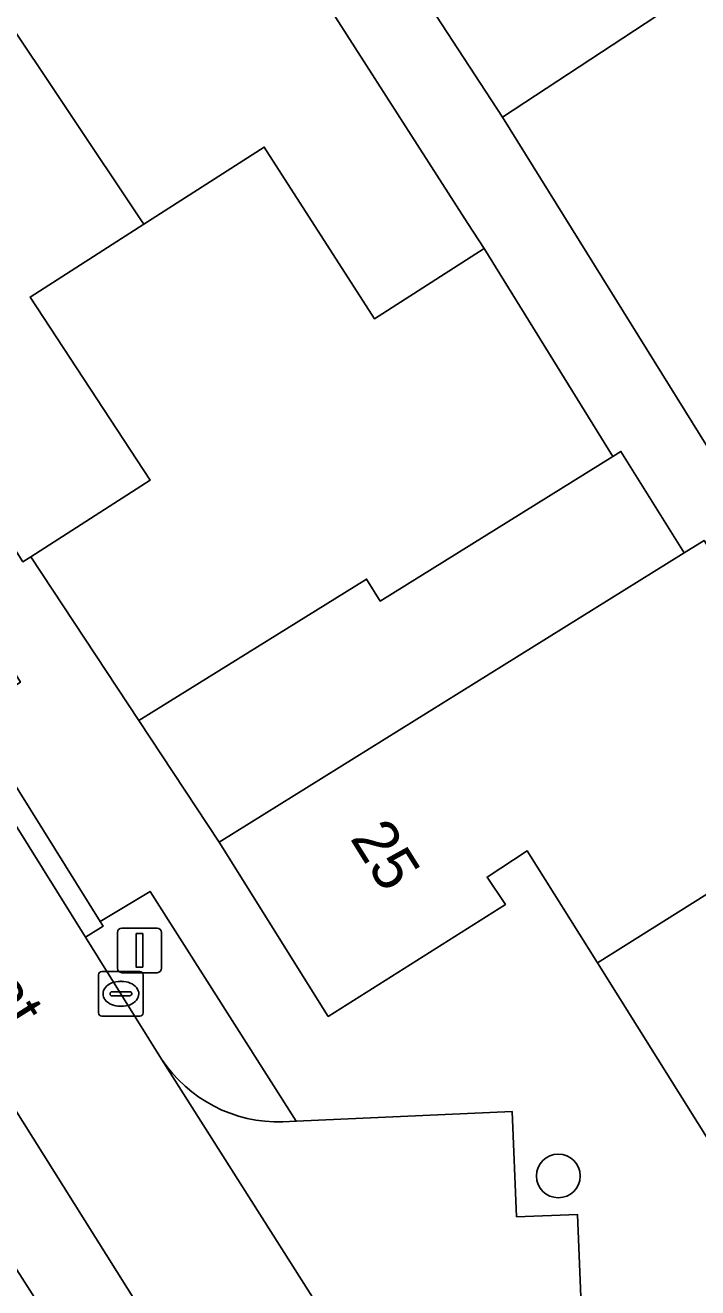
# Model space of a CAD drawing. Extents: x 161798 to 162385, y 382315 to 382833.
# Drawn here: x 162067.75 to 162082.82, y 382537.31 to 382565.6 of the extents above; entities that cross this region are included whole.
import ezdxf

# ---------------------------------------------------------------- set-up
doc = ezdxf.new("R2010")
doc.units = 0
for name, color, linetype in [('IMGEO_Boom', 7, 'Continuous'), ('IMGEO_Erf', 7, 'Continuous'), ('IMGEO_Groenvoorziening', 7, 'Continuous'), ('IMGEO_Kolk', 7, 'Continuous'), ('IMGEO_Lichtmast', 7, 'Continuous'), ('IMGEO_Muur', 7, 'Continuous'), ('IMGEO_Openbare_ruimte_label', 7, 'Continuous'), ('IMGEO_Pand', 7, 'Continuous'), ('IMGEO_Pand_nummerreeks', 7, 'Continuous'), ('IMGEO_Parkeervlak_open', 7, 'Continuous'), ('IMGEO_Rijbaan_lokaal_open', 7, 'Continuous'), ('IMGEO_Voetpad_open', 7, 'Continuous')]:
    doc.layers.add(name, color=color, linetype=linetype)

msp = doc.modelspace()

# ---------------------------------------------------------------- linework, layer by layer
at = {"layer": 'IMGEO_Boom'}
msp.add_circle((162079.693, 382539.814), 0.489, dxfattribs=at)
at = {"layer": 'IMGEO_Erf'}
msp.add_lwpolyline([(162102.649, 382579.449), (162098.622, 382576.803), (162096.601, 382575.476), (162088.533, 382570.177), (162078.441, 382563.548), (162083.732, 382555.037), (162084.772, 382555.684), (162083.299, 382557.955), (162092.219, 382563.711), (162093.688, 382561.433), (162094.761, 382562.125), (162093.279, 382564.418), (162096.865, 382566.737), (162098.358, 382564.461), (162096.539, 382563.28), (162097.699, 382561.493), (162099.947, 382562.953)], dxfattribs=at)
msp.add_lwpolyline([(162078.029, 382560.599), (162075.575, 382559.025), (162073.107, 382562.874), (162070.408, 382561.144), (162067.86, 382559.511), (162070.553, 382555.41), (162067.877, 382553.694), (162070.298, 382550.02), (162075.398, 382553.192), (162075.704, 382552.7), (162080.915, 382555.941)], close=True, dxfattribs=at)
at = {"layer": 'IMGEO_Groenvoorziening'}
for points in [[(162073.52, 382541.026), (162073.822, 382541.04), (162070.549, 382546.192), (162069.427, 382545.515)], [(162069.427, 382545.515), (162069.493, 382545.409), (162069.1, 382545.165), (162070.806, 382542.435)]]:
    msp.add_lwpolyline(points, dxfattribs=at)
msp.add_arc((162073.428, 382544.166), 3.142, 213.4405, 271.6865, dxfattribs=at)
at = {"layer": 'IMGEO_Kolk'}
for p, q in [((162069.393, 382543.47), (162069.393, 382544.322)), ((162069.468, 382544.396), (162070.32, 382544.396)), ((162069.881, 382544.176), (162069.906, 382544.176)), ((162070.394, 382544.322), (162070.394, 382543.47)), ((162069.652, 382543.89), (162069.652, 382543.902)), ((162069.695, 382543.939), (162070.093, 382543.939)), ((162070.136, 382543.902), (162070.136, 382543.89)), ((162070.09, 382543.853), (162069.692, 382543.853)), ((162069.904, 382543.616), (162069.879, 382543.616)), ((162070.32, 382543.396), (162069.468, 382543.396))]:
    msp.add_line(p, q, dxfattribs=at)
for points in [[(162069.393, 382543.47), (162069.393, 382544.322)], [(162069.468, 382544.396), (162070.32, 382544.396)], [(162070.394, 382544.322), (162070.394, 382543.47)], [(162070.32, 382543.396), (162069.468, 382543.396)]]:
    msp.add_lwpolyline(points, dxfattribs=at)
for centre, radius, start, end in [((162069.47, 382544.32), 0.0765, 91.552, 178.448), ((162069.47, 382544.32), 0.0765, 91.552, 178.448), ((162070.318, 382544.32), 0.0765, 1.552, 88.448), ((162070.318, 382544.32), 0.0765, 1.552, 88.448), ((162069.692, 382543.899), 0.0403, 85.8775, 175.7526), ((162069.689, 382543.889), 0.0366, 178.938, 274.7102), ((162070.093, 382543.896), 0.043, 264.8664, 352.4533), ((162070.097, 382543.901), 0.0386, 1.7309, 96.639), ((162069.47, 382543.472), 0.0765, 181.552, 268.448), ((162069.47, 382543.472), 0.0765, 181.552, 268.448), ((162070.318, 382543.472), 0.0765, 271.552, 358.448), ((162070.318, 382543.472), 0.0765, 271.552, 358.448)]:
    msp.add_arc(centre, radius, start, end, dxfattribs=at)
for centre, major_axis, ratio, start_param, end_param in [((162069.88, 382543.896), (-0.387, 0.002), 0.722429, 4.712389, 7.853982), ((162069.905, 382543.896), (-0.39, 0.002), 0.717154, 1.570796, 4.712389)]:
    msp.add_ellipse(centre, major_axis=major_axis, ratio=ratio, start_param=start_param, end_param=end_param, dxfattribs=at)
at = {"layer": 'IMGEO_Lichtmast'}
for p, q in [((162069.914, 382545.37), (162070.704, 382545.37)), ((162070.704, 382545.37), (162069.914, 382545.37)), ((162069.814, 382544.47), (162069.814, 382545.27)), ((162069.814, 382545.27), (162069.814, 382544.47)), ((162070.804, 382545.27), (162070.804, 382544.47)), ((162070.804, 382544.47), (162070.804, 382545.27)), ((162070.704, 382544.37), (162069.914, 382544.37)), ((162069.914, 382544.37), (162070.704, 382544.37))]:
    msp.add_line(p, q, dxfattribs=at)
msp.add_lwpolyline([(162070.234, 382545.245), (162070.384, 382545.245), (162070.384, 382544.495), (162070.234, 382544.495), (162070.234, 382545.245)], dxfattribs=at)
for centre, start, end in [((162069.914, 382545.27), 90, 180), ((162069.914, 382545.27), 90, 180), ((162070.704, 382545.27), 0, 90), ((162070.704, 382545.27), 360, 90), ((162069.914, 382544.47), 180, 270), ((162069.914, 382544.47), 180, 270), ((162070.704, 382544.47), 270, 0), ((162070.704, 382544.47), 270, 0)]:
    msp.add_arc(centre, 0.1, start, end, dxfattribs=at)
at = {"layer": 'IMGEO_Muur'}
msp.add_lwpolyline([(162070.298, 382550.02), (162067.877, 382553.694)], dxfattribs=at)
at = {"layer": 'IMGEO_Pand'}
for points in [[(162083.431, 382577.945), (162079.193, 382575.162), (162078.539, 382576.155), (162076.231, 382574.669), (162076.07, 382574.953), (162075.118, 382574.348), (162075.996, 382573.093), (162073.335, 382571.365), (162076.088, 382567.15), (162078.441, 382563.548), (162088.533, 382570.177)], [(162071.745, 382570.4), (162070.867, 382571.77), (162068.686, 382570.371), (162068.617, 382570.478), (162065.531, 382568.448), (162070.341, 382561.247), (162070.408, 382561.144), (162073.107, 382562.874), (162075.575, 382559.025), (162078.029, 382560.599), (162077.668, 382561.162), (162073.566, 382567.561)], [(162070.408, 382561.144), (162070.341, 382561.247), (162065.531, 382568.448), (162062.645, 382566.55), (162062.571, 382566.665), (162062.299, 382566.491), (162062.308, 382566.308), (162061.202, 382565.599), (162060.346, 382565.051), (162067.224, 382554.323), (162067.7, 382553.581), (162067.877, 382553.694), (162070.553, 382555.41), (162067.86, 382559.511)], [(162082.51, 382553.777), (162081.095, 382556.053), (162080.915, 382555.941), (162075.704, 382552.7), (162075.398, 382553.192), (162070.298, 382550.02), (162072.092, 382547.296)], [(162088.182, 382549.369), (162085.175, 382554.158), (162083.576, 382553.093), (162082.961, 382554.058), (162082.51, 382553.777), (162072.092, 382547.296), (162074.54, 382543.391), (162078.51, 382545.898), (162078.097, 382546.514), (162078.994, 382547.104), (162080.568, 382544.594)], [(162083.278, 382540.272), (162094.271, 382547.166), (162093.121, 382549.025), (162089.719, 382546.92), (162088.182, 382549.369), (162080.568, 382544.594)]]:
    msp.add_lwpolyline(points, close=True, dxfattribs=at)
at = {"layer": 'IMGEO_Parkeervlak_open'}
for points in [[(162076.622, 382526.804), (162062.739, 382548.921)], [(162062.767, 382545.209), (162070.163, 382533.636), (162073.919, 382527.687)], [(162070.806, 382542.435), (162079.529, 382528.674), (162080.1, 382527.774)], [(162080.123, 382538.95), (162078.76, 382538.898), (162078.659, 382541.261), (162073.822, 382541.04), (162073.52, 382541.026)], [(162081.003, 382529.418), (162084.647, 382529.719), (162084.466, 382532.033), (162083.105, 382531.929), (162083.059, 382534.298), (162081.697, 382534.26), (162081.579, 382536.616), (162080.223, 382536.552), (162080.123, 382538.95)]]:
    msp.add_lwpolyline(points, dxfattribs=at)
msp.add_arc((162073.428, 382544.166), 3.142, 213.4405, 271.6865, dxfattribs=at)
at = {"layer": 'IMGEO_Rijbaan_lokaal_open'}
msp.add_lwpolyline([(162055.907, 382559.825), (162061.253, 382551.291), (162061.473, 382550.939), (162062.044, 382550.029), (162062.739, 382548.921), (162076.622, 382526.804), (162079.529, 382528.674), (162070.806, 382542.435), (162069.1, 382545.165), (162066.2, 382549.805)], dxfattribs=at)
at = {"layer": 'IMGEO_Voetpad_open'}
for points in [[(162101.35, 382555.661), (162097.699, 382561.493), (162096.539, 382563.28), (162094.761, 382562.125), (162093.688, 382561.433), (162084.772, 382555.684), (162083.732, 382555.037), (162078.441, 382563.548), (162076.088, 382567.15), (162073.335, 382571.365), (162071.745, 382570.4), (162073.566, 382567.561), (162077.668, 382561.162), (162078.029, 382560.599), (162080.915, 382555.941), (162081.095, 382556.053), (162082.51, 382553.777), (162082.961, 382554.058), (162083.576, 382553.093), (162085.175, 382554.158), (162096.508, 382561.261), (162101.682, 382553.006)], [(162100.624, 382512.613), (162097.64, 382517.372), (162094.758, 382521.967), (162091.965, 382526.421), (162089.081, 382531.02), (162086.288, 382535.473), (162083.278, 382540.272), (162080.568, 382544.594), (162078.994, 382547.104), (162078.097, 382546.514), (162078.51, 382545.898), (162074.54, 382543.391), (162072.092, 382547.296), (162070.298, 382550.02), (162067.877, 382553.694), (162067.7, 382553.581), (162067.224, 382554.323), (162060.346, 382565.051), (162057.798, 382563.184), (162058.339, 382562.28), (162058.445, 382562.115), (162058.477, 382562.063), (162058.51, 382562.012)], [(162066.263, 382552.747), (162066.474, 382552.754), (162067.642, 382550.881), (162066.13, 382549.916), (162066.2, 382549.805), (162066.597, 382550.051), (162069.427, 382545.515), (162070.549, 382546.192), (162073.822, 382541.04), (162078.659, 382541.261), (162078.76, 382538.898), (162080.123, 382538.95), (162080.223, 382536.552), (162081.579, 382536.616), (162081.697, 382534.26), (162083.059, 382534.298), (162083.105, 382531.929), (162084.466, 382532.033), (162084.647, 382529.719), (162081.003, 382529.418)], [(162073.919, 382527.687), (162070.163, 382533.636), (162062.767, 382545.209)]]:
    msp.add_lwpolyline(points, dxfattribs=at)
msp.add_lwpolyline([(162066.597, 382550.051), (162066.2, 382549.805), (162069.1, 382545.165), (162069.493, 382545.409), (162069.427, 382545.515)], close=True, dxfattribs=at)

# ---------------------------------------------------------------- texts
at = {"layer": 'IMGEO_Openbare_ruimte_label'}
msp.add_text('Hoefkestraat', height=1, rotation=302.1329, dxfattribs=at).set_placement((162063.35, 382549.459))
at = {"layer": 'IMGEO_Pand_nummerreeks'}
msp.add_text('25', height=1, rotation=302.0854, dxfattribs=at).set_placement((162075.013, 382547.382))

doc.saveas('drawing.dxf')
